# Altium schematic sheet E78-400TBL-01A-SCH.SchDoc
size A4
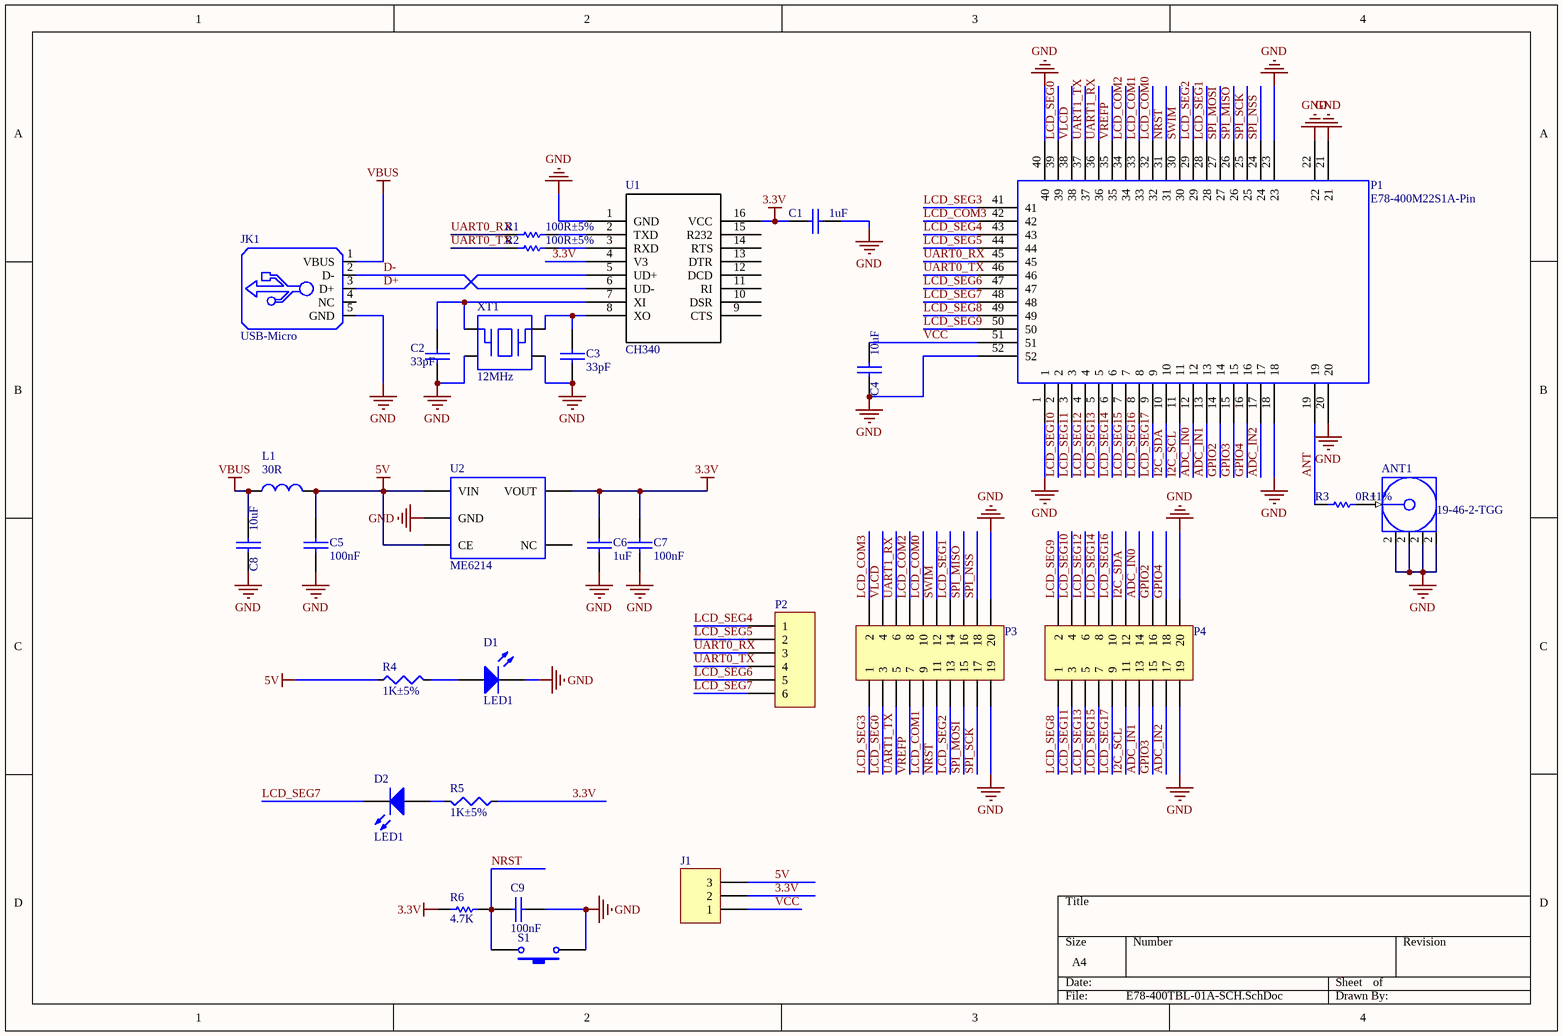
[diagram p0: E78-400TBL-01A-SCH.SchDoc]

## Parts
ANT1  19-46-2-TGG  [E-ANT-SMA-3]
C1  1uF  [E-CAP-0402]
C2  33pF  [E-CAP-0402]
C3  33pF  [E-CAP-0402]
C4  10uF  [E-CAP-0603]
C5  100nF  [E-CAP-0402]
C6  1uF  [E-CAP-0402]
C7  100nF  [E-CAP-0402]
C8  10uF  [E-CAP-0603]
C9  100nF  [E-CAP-0402]
D1  LED1  [E-LED-0805]
D2  LED1  [E-LED-0805]
J1  Header 3  [E-3P-2.54-1]  (value not drawn)
JK1  USB-Micro  [E-Micro USB-5SB]
L1  30R  [E-IND-0603]
P1  E78-400M22S1A-Pin  [E78-400M22S1AA]
P2  Header 6  [E-6P-2.54-1]  (value not drawn)
P3  Header 10X2  [E-10P-2.54-2]  (value not drawn)
P4  Header 10X2  [E-10P-2.54-2]  (value not drawn)
R1  100R±5%  [E-RES-0402]
R2  100R±5%  [E-RES-0402]
R3  0R±1%  [E-RES-0402]
R4  1K±5%  [E-RES-0402]
R5  1K±5%  [E-CAP-0402]
R6  4.7K  [E-RES-0402]
S1  SW-PB  [E-TS3X6X5/2.5]  (value not drawn)
U1  CH340  [E-SOP16]
U2  ME6214  [E-SOT23-5]
XT1  12MHz  [E-XT3225-4]

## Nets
3.3V: C1.1 C6.2 C7.2 J1.2 R5.1 R6.2 U1.4(V3) U1.16(VCC) U2.5(VOUT)
5V: C5.2 J1.3 L1.2 R4.1 U2.1(VIN) U2.3(CE)
GND: ANT1.2(GND) C1.2 C2.1 C3.1 C4.1 C5.1 C6.1 C7.1 C8.1 C9.1 D1.2(K) JK1.5(GND) P1.1 P1.18 P1.20 P1.21 P1.22 P1.23 P1.40 P1.52 P3.19 P3.20 P4.19 P4.20 S1.1 U1.1(GND) U2.2(GND) XT1.3 XT1.4
VBUS: C8.2 JK1.1(VBUS) L1.1
ADC_IN0: P1.12 P4.14
ADC_IN1: P1.13 P4.13
ADC_IN2: P1.17 P4.17
ANT: P1.19 R3.1
D+: JK1.3(D+) U1.5(UD+)
D-: JK1.2(D-) U1.6(UD-)
GPIO2: P1.14 P4.16
GPIO3: P1.15 P4.15
GPIO4: P1.16 P4.18
I2C_SCL: P1.11 P4.11
I2C_SDA: P1.10 P4.12
LCD_COM0: P1.32 P3.10
LCD_COM1: P1.33 P3.9
LCD_COM2: P1.34 P3.8
LCD_COM3: P1.42 P3.2
LCD_SEG0: P1.39 P3.3
LCD_SEG1: P1.28 P3.14
LCD_SEG2: P1.29 P3.13
LCD_SEG3: P1.41 P3.1
LCD_SEG4: P1.43 P2.1
LCD_SEG5: P1.44 P2.2
LCD_SEG6: P1.47 P2.5
LCD_SEG7: D2.2(K) P1.48 P2.6
LCD_SEG8: P1.49 P4.1
LCD_SEG9: P1.50 P4.2
LCD_SEG10: P1.2 P4.4
LCD_SEG11: P1.3 P4.3
LCD_SEG12: P1.4 P4.6
LCD_SEG13: P1.5 P4.5
LCD_SEG14: P1.6 P4.8
LCD_SEG15: P1.7 P4.7
LCD_SEG16: P1.8 P4.10
LCD_SEG17: P1.9 P4.9
NRST: C9.2 P1.31 P3.11 R6.1 S1.2
SPI_MISO: P1.26 P3.16
SPI_MOSI: P1.27 P3.15
SPI_NSS: P1.24 P3.18
SPI_SCK: P1.25 P3.17
SWIM: P1.30 P3.12
UART0_RX: P1.45 P2.3 R1.1
UART0_TX: P1.46 P2.4 R2.1
UART1_RX: P1.36 P3.6
UART1_TX: P1.37 P3.5
VCC: C4.2 J1.1 P1.51
VLCD: P1.38 P3.4
VREFP: P1.35 P3.7
NetANT1_1: ANT1.1(Signal) R3.2
NetC2_2: C2.2 U1.7(XI) XT1.1
NetC3_2: C3.2 U1.8(XO) XT1.2
NetD1_1: D1.1(A) R4.2
NetD2_1: D2.1(A) R5.2
NetR1_2: R1.2 U1.2(TXD)
NetR2_2: R2.2 U1.3(RXD)

Not connected (* = marked no-connect by the designer): JK1 4(NC); U1 9(CTS) 10(DSR) 11(RI) 12(DCD) 13(DTR) 14(RTS) 15(R232); U2 4(NC)

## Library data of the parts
ANT1 = 19-46-2-TGG: SMA RF Coaxial PCB Connector, SM, Vertical Mount Socket, 50 Ohm Impedance
C1-C9 = CAP: Capacitor
D1 D2 = LED1: Typical RED GaAs LED
J1 = Header 3: Header, 3-Pin
JK1 = USB-MINI
L1 = L1B
P1 = E78-400M22S1A
P2 = Header 6: Header, 6-Pin
P3 P4 = Header 10X2: Header, 10-Pin, Dual row
R1-R3 R6 = RES1
R4 R5 = res0603
S1 = SW-PB: Switch
U1 = CH340G
U2 = ME6211
XT1 = XT-SMD1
